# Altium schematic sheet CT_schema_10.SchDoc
size 277 x 170 mm
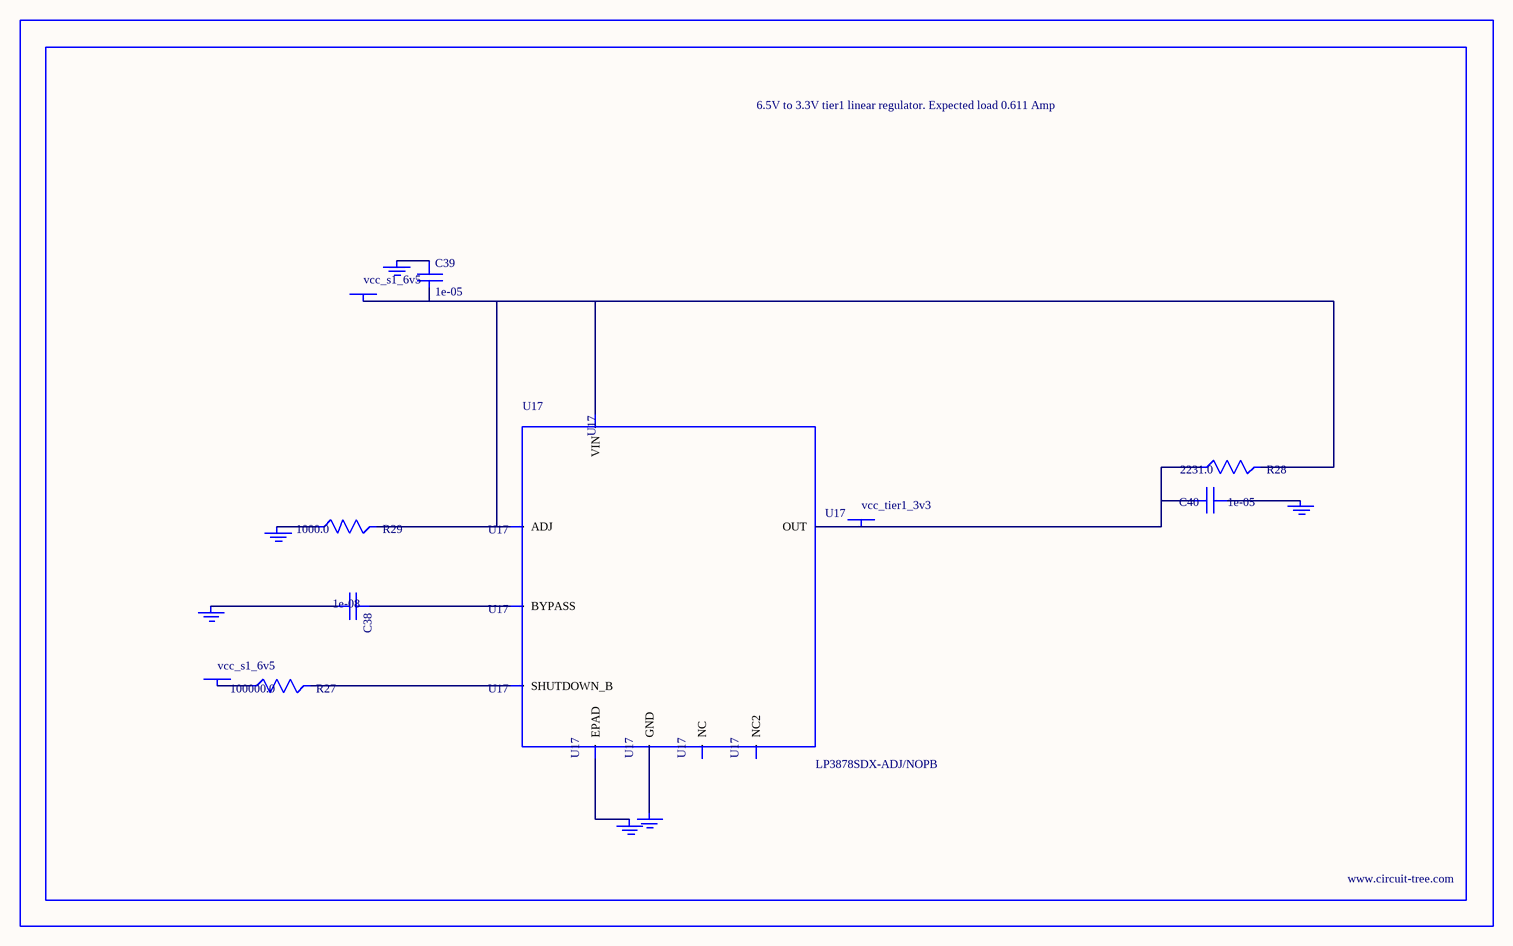
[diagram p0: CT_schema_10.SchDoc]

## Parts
BORDER9  (no value)
C38  1e-08  [C0402]
C39  1e-05  [C1206]
C40  1e-05  [C1210]
GND_INSTANCE_9_0  (no value)
GND_INSTANCE_9_1  (no value)
GND_INSTANCE_9_2  (no value)
GND_INSTANCE_9_3  (no value)
GND_INSTANCE_9_4  (no value)
GND_INSTANCE_9_5  (no value)
POWER_INSTANCE_9_0  vcc_s1_6v5
POWER_INSTANCE_9_1  vcc_s1_6v5
POWER_INSTANCE_9_2  vcc_tier1_3v3
R27  100000.0  [R0603]
R28  2231.0  [R0603]
R29  1000.0  [R0603]
U17  LP3878SDX-ADJ/NOPB  [WSON-8]

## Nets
NetC38_1: C38.1 U17.1(BYPASS)
NetC38_2: C38.2 GND_INSTANCE_9_0.0(GND)
NetC39_1: C39.1 GND_INSTANCE_9_1.0(GND)
NetC39_2: C39.2 POWER_INSTANCE_9_0.0(PWR) R28.2 R29.2 U17.4(VIN) U17.6(ADJ)
NetC40_1: C40.1 GND_INSTANCE_9_2.0(GND)
NetC40_2: C40.2 POWER_INSTANCE_9_2.0(PWR) R28.1 U17.5(OUT)
NetGND_INSTANCE_9_3_0: GND_INSTANCE_9_3.0(GND) R29.1
NetGND_INSTANCE_9_4_0: GND_INSTANCE_9_4.0(GND) U17.PAD(EPAD)
NetGND_INSTANCE_9_5_0: GND_INSTANCE_9_5.0(GND) U17.3(GND)
NetPOWER_INSTANCE_9_1_0: POWER_INSTANCE_9_1.0(PWR) R27.1
NetR27_2: R27.2 U17.8(SHUTDOWN_B)

Not connected (* = marked no-connect by the designer): U17 2(NC) 7(NC2)

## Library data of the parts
BORDER9 = BORDER_PAGE9
C38 = C0402C103K3RAC
C39 = C1206C106K3RACTU
C40 = GRM32DR61E106MA12L
GND_INSTANCE_9_0-GND_INSTANCE_9_5 = GND
POWER_INSTANCE_9_0-POWER_INSTANCE_9_2 = PWR
R27 = RC0603JR-07100KL
R28 = R28
R29 = RC0603JR-071KL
